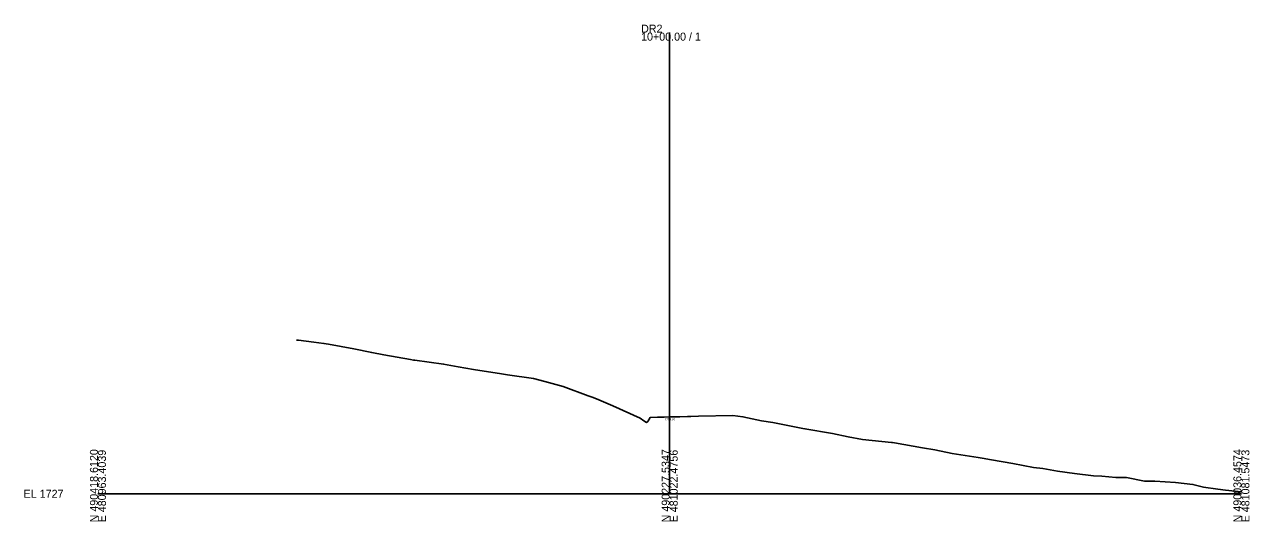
# Model space of a CAD drawing. Extents: x -26 to 403, y -10 to 2576.
# Drawn here: x -25.7 to 402.8, y -9.7 to 164.1 of the extents above; entities that cross this region are included whole.
import ezdxf

# ---------------------------------------------------------------- set-up
doc = ezdxf.new("R2010")
doc.units = 0
for name, color, linetype in [('Exist Cross Section Cell', 7, 'Continuous'), ('Exist XS Center Line Elevation Label', 7, 'Continuous'), ('Exist XS Ground Line', 7, 'Continuous')]:
    doc.layers.add(name, color=color, linetype=linetype)

msp = doc.modelspace()

# ---------------------------------------------------------------- linework, layer by layer
at = {"layer": 'Exist Cross Section Cell'}
for p, q in [((200, 0), (200, 161.3)), ((0, 0), (200, 0)), ((200, 0), (400, 0))]:
    msp.add_line(p, q, dxfattribs=at)
at = {"layer": 'Exist XS Ground Line'}
msp.add_lwpolyline([(69.5, 53.77), (70.21, 53.71), (75.53, 53.07), (79.04, 52.58), (80.6, 52.32), (89.5, 50.71), (95.76, 49.41), (99.97, 48.62), (109.39, 46.96), (110.44, 46.79), (110.91, 46.73), (120.91, 45.34), (126.06, 44.4), (131.38, 43.46), (141.22, 41.92), (141.85, 41.82), (143.26, 41.62), (152.32, 40.3), (156.37, 39.25), (162.79, 37.53), (171.53, 34.31), (173.26, 33.7), (175.27, 32.85), (180.15, 30.73), (189.69, 26.44), (191.01, 25.55), (191.94, 24.96), (192.4, 25.31), (193.14, 26.65), (195.77, 26.77), (196.27, 26.81), (198.04, 26.85), (200, 26.89), (203.55, 26.97), (206.22, 27.03), (207.41, 27.08), (210.1, 27.11), (222.15, 27.33), (225.6, 26.92), (232.14, 25.53), (236.07, 24.89), (244.85, 23.17), (246.54, 22.84), (247.29, 22.72), (257.01, 21.08), (262.45, 19.92), (267.48, 19), (277.6, 17.99), (277.95, 17.94), (278.71, 17.82), (288.42, 16.09), (292.76, 15.36), (298.88, 14.12), (307.91, 12.67), (309.35, 12.43), (312.58, 11.93), (320.01, 10.62), (327.24, 9.24), (330.54, 8.79), (335.7, 7.95), (341.66, 7.09), (348.25, 6.23), (351.23, 6.16), (356.13, 5.74), (359.76, 5.7), (366.07, 4.47), (369.78, 4.42), (376.98, 3.99), (383.07, 3.3), (386.76, 2.35), (391.82, 1.64), (394.4, 1.28), (400, 0.63)], dxfattribs=at)

# ---------------------------------------------------------------- texts
at = {"layer": 'Exist Cross Section Cell'}
for s, p in [('DR2', (190, 161.3)), ('10+00.00 / 1', (190, 158.5)), ('EL 1727', (-26, -1.4))]:
    msp.add_text(s, height=2.8, dxfattribs=at).set_placement(p)
for s, p in [('N 490418.6120', (0, -10)), ('E 480963.4039', (2.8, -10)), ('N 490227.5347', (200, -10)), ('E 481022.4756', (202.8, -10)), ('N 490036.4574', (400, -10)), ('E 481081.5473', (402.8, -10))]:
    msp.add_text(s, height=2.8, rotation=90, dxfattribs=at).set_placement(p)
at = {"layer": 'Exist XS Center Line Elevation Label'}
msp.add_text('1753.89', height=0.75, dxfattribs=at).set_placement((198.23, 25.64))

doc.saveas('drawing.dxf')
